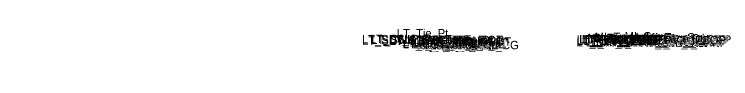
# Model space of a CAD drawing. Extents: x -26 to 4229, y -10 to 9523.
# Drawn here: x 3000 to 3171.5, y 4500 to 4508.6 of the extents above; entities that cross this region are included whole.
import ezdxf

# ---------------------------------------------------------------- set-up
doc = ezdxf.new("R2010")
doc.units = 0
doc.layers.add('Default', color=7, linetype='Continuous')

msp = doc.modelspace()

# ---------------------------------------------------------------- texts
at = {"layer": 'Default'}
for s, height, p in [('LT_Tie_Pt', 2, (3091.58, 4506.48)), ('LT_SDWK_Out_Top', 2, (3083.24, 4505.07)), ('LT_SDWK_Out_Bot', 2, (3083.27, 4504.74)), ('LT_CSLP_Pnt', 2, (3085.17, 4505.1)), ('LT_Sub_Trench_Out_DLT', 2, (3085.49, 4504.9)), ('LT_SDWK_In_Top', 2, (3089.86, 4504.97)), ('LT_SDWK_In_Bot', 2, (3089.89, 4504.64)), ('LT_CG_Top_Face', 2, (3094.76, 4504.86)), ('LT_CG_Top_BOC', 2, (3095.28, 4504.86)), ('LT_PV1_OEOT', 2, (3100.24, 4504.48)), ('LT_PV2_OEEOP', 2, (3134.69, 4504.94)), ('LT_PV3_OEEOP', 2, (3134.69, 4504.69)), ('LT_PV1_OEEOP', 2, (3135.26, 4505.07)), ('LT_PV2_IEEOP', 2, (3135.34, 4504.94)), ('LT_PV1_IEEOP', 2, (3135.91, 4505.07)), ('LT_PV2_PGL1', 2, (3136.27, 4504.94)), ('LT_PV3_PGL1', 2, (3136.27, 4504.69)), ('LT_PV2_PGL', 2, (3136.6, 4504.94)), ('LT_PV1_PGL', 2, (3137.17, 4505.19)), ('MI_Face In', 2, (3137.29, 4505.36)), ('MI_Bot In', 2, (3138.27, 4505.19)), ('MI_Top In', 2, (3139, 4505.61)), ('MI_Crown', 2, (3146.14, 4505.75)), ('RT_PV2_OEEOP', 2, (3150.01, 4504.82)), ('RT_PV3_OEEOP', 2, (3150.01, 4504.57)), ('RT_PV1_OEEOP', 2, (3150.58, 4504.95)), ('RT_PV2_IEEOP', 2, (3150.66, 4504.82)), ('MI_Face Out', 2, (3151.01, 4505.24)), ('MI_Top Out', 2, (3151.22, 4505.49)), ('RT_PV1_IEEOP', 2, (3151.22, 4504.95)), ('RT_PV2_PGL1', 2, (3151.58, 4504.82)), ('RT_PV3_PGL1', 2, (3151.58, 4504.57)), ('RT_PV2_PGL', 2, (3151.92, 4504.82)), ('MI_Bot Out', 2, (3152.01, 4505.07)), ('RT_PV1_PGL', 2, (3152.48, 4505.07)), ('LT_CG1_Shelf_Out', 2, (3093.05, 4503.83)), ('LT_CG_Bot_BOC', 2, (3095.31, 4503.84)), ('LT_CG_Top_Gut', 2, (3095.74, 4504.36)), ('LT_Sub_OEOP', 2, (3096.36, 4503.58)), ('LT_Sub_OEOT_CG', 2, (3096.87, 4503.64)), ('LT_CG_Bot_IE', 2, (3099.41, 4503.89)), ('LT_Sub_OEOT', 2, (3099.58, 4503.6)), ('LT_PV2_OEOT', 2, (3099.67, 4504.23)), ('LT_PV3_OEOT', 2, (3099.67, 4503.98)), ('LT_Sub_OEEOP', 2, (3134.6, 4504.32)), ('LT_PV4_PGL', 2, (3136.6, 4504.32)), ('RT_Sub_OEEOP', 2, (3149.92, 4504.2)), ('RT_PV4_PGL', 2, (3151.92, 4504.2)), ('-', 0.0001, (3000, 4500)), ('-', 0.0001, (3000, 4500)), ('-', 0.0001, (3000, 4500)), ('-', 0.0001, (3000, 4500)), ('-', 0.0001, (3000, 4500)), ('-', 0.0001, (3000, 4500)), ('-', 0.0001, (3000, 4500))]:
    msp.add_text(s, height=height, dxfattribs=at).set_placement(p)

doc.saveas('drawing.dxf')
